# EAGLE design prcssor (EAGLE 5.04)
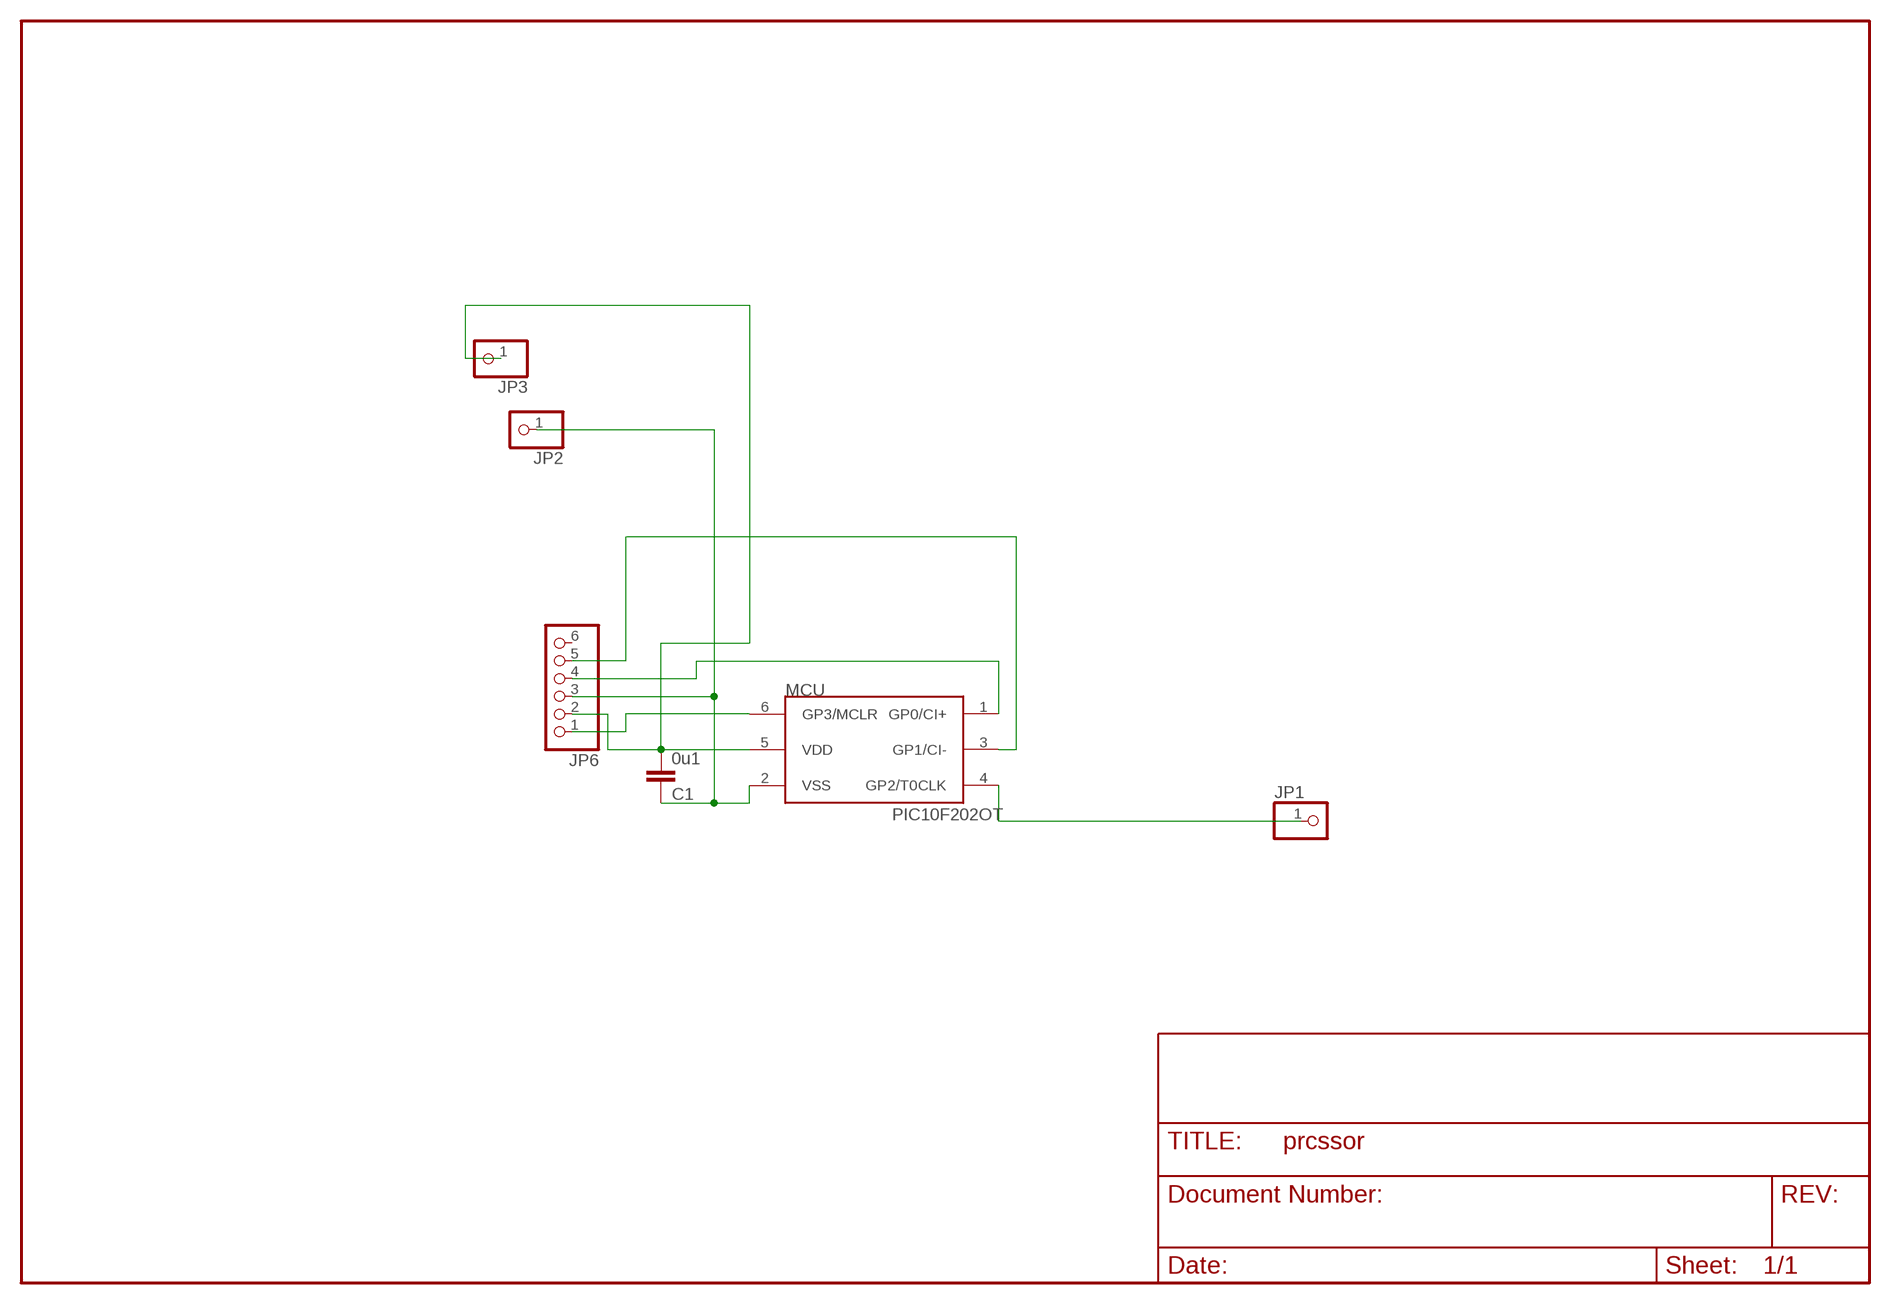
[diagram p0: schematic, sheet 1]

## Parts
C1  0u1  C-EUC1206  [C1206]
JP1  PINHD-1X1  [1X01]
JP2  PINHD-1X1  [1X01]
JP3  PINHD-1X1  [1X01]
JP6  PINHD-1X6  [1X06]
MCU  PIC10F202OT  [SOT23-6]

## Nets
GP0: JP6.4 MCU.1(GP0/CI+)
GP1: JP6.5 MCU.3(GP1/CI-)
GP2: JP1.1 MCU.4(GP2/T0CLK)
GP3: JP6.1 MCU.6(GP3/MCLR)
VDD1: C1.2 JP3.1 JP6.2 MCU.5(VDD)
VSS1: C1.1 JP2.1 JP6.3 MCU.2(VSS)
Unconnected: JP6.6

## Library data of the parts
C1 = rcl:C-EU: CAPACITOR, European symbol
JP1-JP3 = pinhead(2):PINHD-1X1: PIN HEADER
JP6 = pinhead(2):PINHD-1X6: PIN HEADER
MCU = microchip-3:PIC10F2*: uPC nW 0,25/0,5k Program Flash memory Comparator

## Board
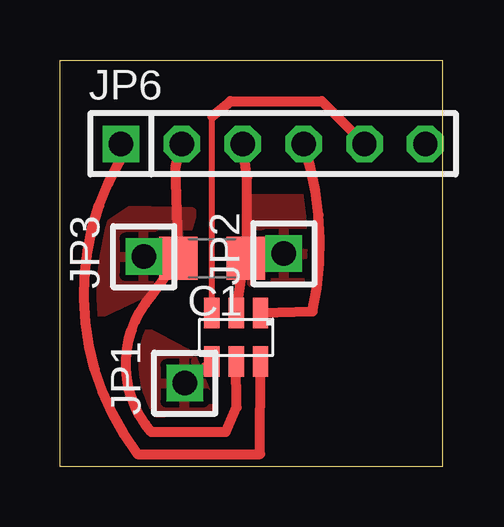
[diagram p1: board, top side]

Size 15.94 x 16.95 mm. Coordinates in mm from the lower left corner, seen from the top.
Outline: 0,0 0,16.95 15.94,16.95 15.94,0 0,0
Copper layers (1*16): Top 0.035mm / dielectric 1.5mm / Bottom 0.035mm
Design rules "default": minimum track width 10mil, minimum drill 24mil, track to track 8mil, track to pad 8mil, pad to pad 8mil, via to via 8mil, smd to smd 8mil, copper to edge 40mil, drill to drill 8mil, minimum pad ring 10mil, minimum via ring 8mil, stop-mask expansion 4mil, vias tented up to drill 0mil, thermal gap 10mil

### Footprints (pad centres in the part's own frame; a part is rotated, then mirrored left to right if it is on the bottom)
C1206 = smd 1.6 x 1.8: 1 -1.4,0; 2 1.4,0
1X01 = drill 1.016 square: 1 0,0
1X06 = drill 1.016 square: 1 -6.35,0 | drill 1.016 octagon: 2 -3.81,0; 3 -1.27,0; 4 1.27,0; 5 3.81,0; 6 6.35,0
SOT23-6 = smd 0.635 x 1.27: 1 -1.016,-1.016; 2 0,-1.016; 3 1.016,-1.016; 4 1.016,1.016; 5 0,1.016; 6 -1.016,1.016

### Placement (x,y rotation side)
C1  6.35,8.7 180 top
JP1  5.21,3.49 90 top
JP2  9.33,8.89 90 top
JP3  3.49,8.76 90 top
JP6  8.89,13.46 0 top
MCU  7.35,5.4 180 top

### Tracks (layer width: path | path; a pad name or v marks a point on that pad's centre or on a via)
GP0
  Top 0.406: JP6.4 arc-31 10.54,6.48 MCU.1
GP1
  Top 0.254: MCU.3 6.35,14.61
  Top 0.406: 6.35,14.61 7.11,15.24 10.92,15.24 JP6.5
GP2
  Top 0.406: JP1.1 MCU.4
  pour Top (isolate 0.305): 6.41,2.35 3.37,2.22 3.56,5.65 5.46,4.64
GP3
  Top 0.406: MCU.6 8.35,0.54 3.24,0.54 arc-67 2.48,12.7 JP6.1
VDD1
  Top 0.406: MCU.5 7.37,2.48 6.92,1.46 3.81,1.46 arc-82 3.81,7.11 C1.2 | C1.2 3.56,8.7 JP3.1 | JP6.2 4.83,12.51 C1.2
  pour Top (isolate 0.305): 2.92,10.67 1.4,9.65 1.52,6.35 4.7,7.81 5.52,10.6
VSS1
  Top 0.406: MCU.2 7.75,9.02 7.8,9.21 | JP2.1 9.14,8.7 C1.1 7.8,9.21 | JP6.3 7.81,12.06 7.81,9.27 7.8,9.21
  pour Top (isolate 0.305): 7.81,11.18 10.16,11.18 10.22,7.68 8,7.68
